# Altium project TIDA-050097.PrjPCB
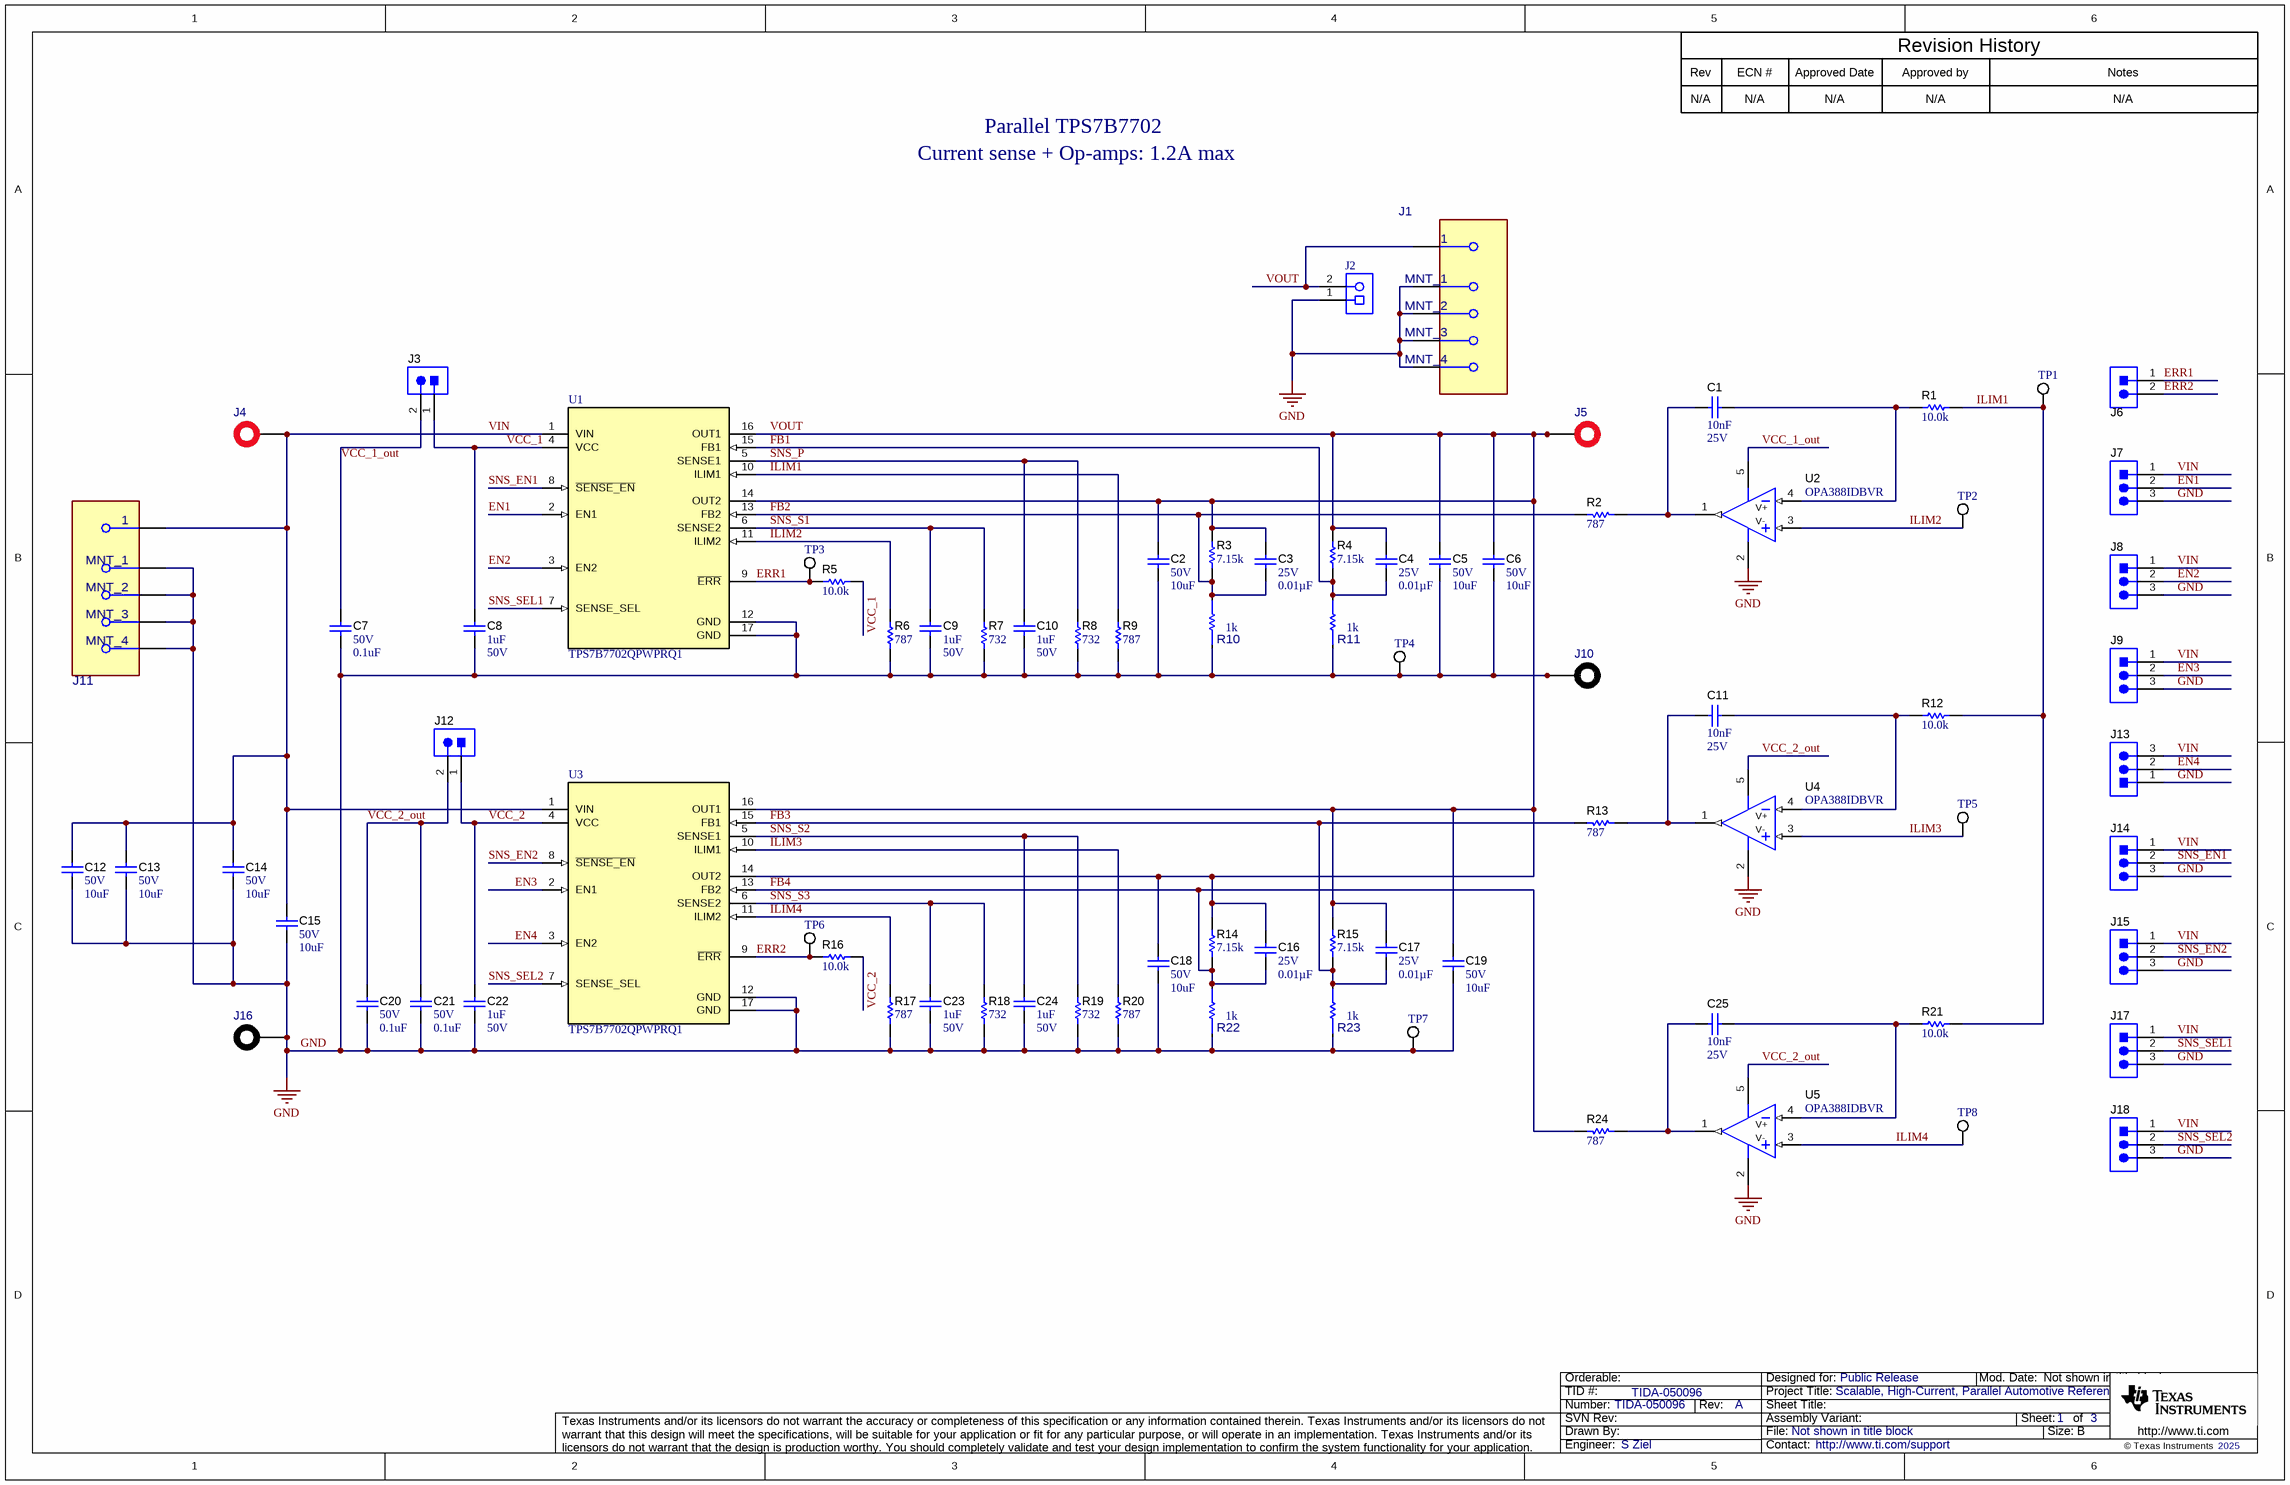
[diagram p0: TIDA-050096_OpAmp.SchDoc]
TID: TIDA-050096; TechSupport: http://www.ti.com/support; SCH_Rev: A; PRJ_Title: Scalable, High-Current, Parallel Automotive Reference Design; PRJ_Number: TIDA-050096; PRJ_Engineer: S Ziel; PRJ_Customer: Public Release; PCB_Rev: A; PCB_Layout: S Ziel; CopyrightYear: 2025
3 sheets, 143 parts. Net scope: global (net labels, ports and power ports of the same name join across sheets).
Board file: TIDA-050096_PCB.PcbDoc
Sheets:
  TIDA-050096_OpAmp.SchDoc
  TIDA-050096_Hardware.SchDoc
  TIDA-050096_Ballast.SchDoc

## Sheet TIDA-050096_OpAmp.SchDoc
size 431 x 279 mm; Date: Not shown in title block; ApprovedBy: Not shown in title block; CheckedBy: Not shown in title block; Author: Not shown in title block; CompanyName: Not shown in title block; Engineer: Not shown in title block; Organization: Not shown in title block; Address1: Not shown in title block; Address2: Not shown in title block; Address3: Not shown in title block; Address4: Not shown in title block; DocumentNumber: 1; Revision: Use project parameter SCH_Rev; SheetNumber: 1; SheetTotal: 3; PageSetup: Record=PageOptions¦CenterHorizontal=True¦CenterVertical=True¦PrintScale=1.00¦XCorrection=1.00¦YCorrection=1.00¦PrintKind=0¦BorderSize=5000000¦LeftOffset=0¦BottomOffset=0¦Orientation=2¦PaperLength=1000¦PaperWidth=1000¦Scale=100¦PaperSource=15¦PrintQuality=600¦MediaType=1¦DitherType=10¦PaperKind=Letter¦PrintScaleMode=1

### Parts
C1  Cap_F: 10nF  VDC_V: 25V  [0402]  (hidden comment: 04023C103JAT2A)
C2  VDC_V: 50V  ValueDisplayed: 10uF  [1210_270]  (hidden comment: GRM32ER71H106KA12L)
C3  VDC_V: 25V  ValueDisplayed: 0.01µF  [0402]  (hidden comment: 04023C103JAT2A)
C4  VDC_V: 25V  ValueDisplayed: 0.01µF  [0402]  (hidden comment: 04023C103JAT2A)
C5  VDC_V: 50V  ValueDisplayed: 10uF  [1210_270]  (hidden comment: GRM32ER71H106KA12L)
C6  VDC_V: 50V  ValueDisplayed: 10uF  [1210_270]  (hidden comment: GRM32ER71H106KA12L)
C7  VDC_V: 50V  ValueDisplayed: 0.1uF  [0402]  (hidden comment: C1005X7R1H104K050BE)
C8  ValueDisplayed: 1uF  VDC_V: 50V  [0603]  (hidden comment: GRM188R61H105KAALD)
C9  ValueDisplayed: 1uF  VDC_V: 50V  [0603]  (hidden comment: GRM188R61H105KAALD)
C10  ValueDisplayed: 1uF  VDC_V: 50V  [0603]  (hidden comment: GRM188R61H105KAALD)
C11  Cap_F: 10nF  VDC_V: 25V  [0402]  (hidden comment: 04023C103JAT2A)
C12  VDC_V: 50V  ValueDisplayed: 10uF  [1210_270]  (hidden comment: GRM32ER71H106KA12L)
C13  VDC_V: 50V  ValueDisplayed: 10uF  [1210_270]  (hidden comment: GRM32ER71H106KA12L)
C14  VDC_V: 50V  ValueDisplayed: 10uF  [1210_270]  (hidden comment: GRM32ER71H106KA12L)
C15  VDC_V: 50V  ValueDisplayed: 10uF  [1210_270]  (hidden comment: GRM32ER71H106KA12L)
C16  VDC_V: 25V  ValueDisplayed: 0.01µF  [0402]  (hidden comment: 04023C103JAT2A)
C17  VDC_V: 25V  ValueDisplayed: 0.01µF  [0402]  (hidden comment: 04023C103JAT2A)
C18  VDC_V: 50V  ValueDisplayed: 10uF  [1210_270]  (hidden comment: GRM32ER71H106KA12L)
C19  VDC_V: 50V  ValueDisplayed: 10uF  [1210_270]  (hidden comment: GRM32ER71H106KA12L)
C20  VDC_V: 50V  ValueDisplayed: 0.1uF  [0402]  (hidden comment: C1005X7R1H104K050BE)
C21  VDC_V: 50V  ValueDisplayed: 0.1uF  [0402]  (hidden comment: C1005X7R1H104K050BE)
C22  ValueDisplayed: 1uF  VDC_V: 50V  [0603]  (hidden comment: GRM188R61H105KAALD)
C23  ValueDisplayed: 1uF  VDC_V: 50V  [0603]  (hidden comment: GRM188R61H105KAALD)
C24  ValueDisplayed: 1uF  VDC_V: 50V  [0603]  (hidden comment: GRM188R61H105KAALD)
C25  Cap_F: 10nF  VDC_V: 25V  [0402]  (hidden comment: 04023C103JAT2A)
J1  RF12-07H-T-00-50-G  [FP-RF12-07H-T-00-50-G_CONN_MMCX-MFG]  (value not drawn)
J2  691 101 710 002  [Wurth_691101710002]  (value not drawn)
J3  PBC02SAAN  [Sullins_PBC02SAAN]  (value not drawn)
J4  571-0500  [571-0500]  (value not drawn)
J5  571-0500  [571-0500]  (value not drawn)
J6  PBC02SAAN  [Sullins_PBC02SAAN]  (value not drawn)
J7  61300311121  [WURTH_61300311121]  (value not drawn)
J8  61300311121  [WURTH_61300311121]  (value not drawn)
J9  61300311121  [WURTH_61300311121]  (value not drawn)
J10  571-0100  [571-0100]  (value not drawn)
J11  RF12-07H-T-00-50-G  [FP-RF12-07H-T-00-50-G_CONN_MMCX-MFG]  (value not drawn)
J12  PBC02SAAN  [Sullins_PBC02SAAN]  (value not drawn)
J13  61300311121  [WURTH_61300311121]  (value not drawn)
J14  61300311121  [WURTH_61300311121]  (value not drawn)
J15  61300311121  [WURTH_61300311121]  (value not drawn)
J16  571-0100  [571-0100]  (value not drawn)
J17  61300311121  [WURTH_61300311121]  (value not drawn)
J18  61300311121  [WURTH_61300311121]  (value not drawn)
R1  ValueDisplayed: 10.0k  [0603]  (hidden comment: RC0603FR-0710KL)
R2  ValueDisplayed: 787  [0603]  (hidden comment: RC0603FR-07787RL)
R3  ValueDisplayed: 7.15k  [0402]  (hidden comment: CRCW04027K15FKED)
R4  ValueDisplayed: 7.15k  [0402]  (hidden comment: CRCW04027K15FKED)
R5  ValueDisplayed: 10.0k  [0603]  (hidden comment: RC0603FR-0710KL)
R6  ValueDisplayed: 787  [0603]  (hidden comment: RC0603FR-07787RL)
R7  ValueDisplayed: 732  [0402]  (hidden comment: CRCW0402732RFKED)
R8  ValueDisplayed: 732  [0402]  (hidden comment: CRCW0402732RFKED)
R9  ValueDisplayed: 787  [0603]  (hidden comment: RC0603FR-07787RL)
R10  value 1k  [FP-RC0402FR-071KL_0402-IPC_A]  (hidden comment: RC0402FR-071KL)
R11  value 1k  [FP-RC0402FR-071KL_0402-IPC_A]  (hidden comment: RC0402FR-071KL)
R12  ValueDisplayed: 10.0k  [0603]  (hidden comment: RC0603FR-0710KL)
R13  ValueDisplayed: 787  [0603]  (hidden comment: RC0603FR-07787RL)
R14  ValueDisplayed: 7.15k  [0402]  (hidden comment: CRCW04027K15FKED)
R15  ValueDisplayed: 7.15k  [0402]  (hidden comment: CRCW04027K15FKED)
R16  ValueDisplayed: 10.0k  [0603]  (hidden comment: RC0603FR-0710KL)
R17  ValueDisplayed: 787  [0603]  (hidden comment: RC0603FR-07787RL)
R18  ValueDisplayed: 732  [0402]  (hidden comment: CRCW0402732RFKED)
R19  ValueDisplayed: 732  [0402]  (hidden comment: CRCW0402732RFKED)
R20  ValueDisplayed: 787  [0603]  (hidden comment: RC0603FR-07787RL)
R21  ValueDisplayed: 10.0k  [0603]  (hidden comment: RC0603FR-0710KL)
R22  value 1k  [FP-RC0402FR-071KL_0402-IPC_A]  (hidden comment: RC0402FR-071KL)
R23  value 1k  [FP-RC0402FR-071KL_0402-IPC_A]  (hidden comment: RC0402FR-071KL)
R24  ValueDisplayed: 787  [0603]  (hidden comment: RC0603FR-07787RL)
TP1  5016  [Testpoint_Keystone_Compact]  (value not drawn)
TP2  5016  [Testpoint_Keystone_Compact]  (value not drawn)
TP3  5016  [Testpoint_Keystone_Compact]  (value not drawn)
TP4  5016  [Testpoint_Keystone_Compact]  (value not drawn)
TP5  5016  [Testpoint_Keystone_Compact]  (value not drawn)
TP6  5016  [Testpoint_Keystone_Compact]  (value not drawn)
TP7  5016  [Testpoint_Keystone_Compact]  (value not drawn)
TP8  5016  [Testpoint_Keystone_Compact]  (value not drawn)
U1  TPS7B7702QPWPRQ1  [PWP0016J_N]
U2  OPA388IDBVR  [DBV0005A_N]
U3  TPS7B7702QPWPRQ1  [PWP0016J_N]
U4  OPA388IDBVR  [DBV0005A_N]
U5  OPA388IDBVR  [DBV0005A_N]

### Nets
GND: C2.2 C5.2 C6.2 C7.2 C8.1 C9.1 C10.1 C12.2 C13.2 C14.2 C15.2 C18.2 C19.2 C20.2 C21.2 C22.2 C23.1 C24.1 J1.2(MNT_1) J1.3(MNT_2) J1.4(MNT_3) J1.5(MNT_4) J2.1 J7.3 J8.3 J9.3 J10.1 J10.2 J11.2(MNT_1) J11.3(MNT_2) J11.4(MNT_3) J11.5(MNT_4) J13.1 J14.3 J15.3 J16.1 J16.2 J17.3 J18.3 R6.1 R7.1 R8.1 R9.1 R10.1 R11.1 R17.1 R18.1 R19.1 R20.1 R22.1 R23.1 TP4.1 TP7.1 U1.12(GND) U1.17(GND) U2.2(V-) U3.12(GND) U3.17(GND) U4.2(V-) U5.2(V-)
EN1: J7.2 U1.2(EN1)
EN2: J8.2 U1.3(EN2)
EN3: J9.2 U3.2(EN1)
EN4: J13.2 U3.3(EN2)
ERR1: J6.1 R5.2 TP3.1 U1.9(~{ERR})
ERR2: J6.2 R16.2 TP6.1 U3.9(~{ERR})
FB1: C4.2 R4.2 R11.2 U1.15(FB1)
FB2: C3.2 R2.2 R3.2 R10.2 U1.13(FB2)
FB3: C17.2 R13.2 R15.2 R23.2 U3.15(FB1)
FB4: C16.2 R14.2 R22.2 R24.2 U3.13(FB2)
ILIM1: R1.1 R9.2 R12.1 R21.1 TP1.1 U1.10(ILIM1)
ILIM2: R6.2 TP2.1 U1.11(ILIM2) U2.3(IN+)
ILIM3: R20.2 TP5.1 U3.10(ILIM1) U4.3(IN+)
ILIM4: R17.2 TP8.1 U3.11(ILIM2) U5.3(IN+)
SNS_EN1: J14.2 U1.8(~{SENSE_EN})
SNS_EN2: J15.2 U3.8(~{SENSE_EN})
SNS_P: C10.2 R8.2 U1.5(SENSE1)
SNS_S1: C9.2 R7.2 U1.6(SENSE2)
SNS_S2: C24.2 R19.2 U3.5(SENSE1)
SNS_S3: C23.2 R18.2 U3.6(SENSE2)
SNS_SEL1: J17.2 U1.7(SENSE_SEL)
SNS_SEL2: J18.2 U3.7(SENSE_SEL)
VCC_1: C8.2 J3.1 R5.1 U1.4(VCC)
VCC_1_out: C7.1 J3.2 U2.5(V+)
VCC_2: C22.1 J12.1 R16.1 U3.4(VCC)
VCC_2_out: C20.1 C21.1 J12.2 U4.5(V+) U5.5(V+)
VIN: C12.1 C13.1 C14.1 C15.1 J4.1 J4.2 J7.1 J8.1 J9.1 J11.1 J13.3 J14.1 J15.1 J17.1 J18.1 U1.1(VIN) U3.1(VIN)
VOUT: C2.1 C3.1 C4.1 C5.1 C6.1 C16.1 C17.1 C18.1 C19.1 J1.1 J2.2 J5.1 J5.2 R3.1 R4.1 R14.1 R15.1 U1.14(OUT2) U1.16(OUT1) U3.14(OUT2) U3.16(OUT1)
NetC1_1: C1.1 R1.2 U2.4(IN-)
NetC1_2: C1.2 R2.1 U2.1(OUT)
NetC11_1: C11.1 R12.2 U4.4(IN-)
NetC11_2: C11.2 R13.1 U4.1(OUT)
NetC25_1: C25.1 R21.2 U5.4(IN-)
NetC25_2: C25.2 R24.1 U5.1(OUT)

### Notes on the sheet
- Rev
- N/A
- ECN #
- Approved Date
- Approved by
- Revision History
- Notes
- Current sense + Op-amps: 1.2A max
- Parallel TPS7B7702

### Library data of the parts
C1 C11 C25 = CMP-0085568-1: CAP, CERM, 0.01 µF, 25 V,+/- 5%, X7R, 0402; Manufacturer: AVX; TaMin_C: -55°C; Polarized: N; SizeAreaWB_mm2: 3; U/M: EA; Value: 0.01uF; TaMax_C: 125°C; SizeZ_mm: 0.6; SizeX_mm: 1; SizeY_mm: 0.5; AEC Category: Q200; ValueDisplayed: 0.01µF
C2 C5 C6 C12-C15 C18 C19 = CMP-0009226-3: CAP, CERM, 10 uF, 50 V, +/- 10%, X7R, 1210; Manufacturer: MuRata; TaMin_C: -55°C; Polarized: N; SizeAreaWB_mm2: 14.7; Value1: Unknown; U/M: EA; Value: 10uF; TaMax_C: 125°C; SizeZ_mm: 2.7; SizeX_mm: 3.2; SizeY_mm: 2.5; Cap_Case: 1210; SizeArea_mm2: 8; Cap_F: 10µF; AEC Category: Q200
C3 C4 C16 C17 = CMP-0085568-1: CAP, CERM, 0.01 µF, 25 V,+/- 5%, X7R, 0402; Manufacturer: AVX; Value: 0.01uF; SizeZ_mm: 0.6; AEC Qualified: N; Cap_F: 10nF; AEC Category: Q200; SizeAreaWB_mm2: 3; SizeArea_mm2: 0.5; TaMin_C: -55°C; U/M: EA; SizeX_mm: 1; TaMax_C: 125°C
C7 C20 C21 = CMP-0064946-2: CAP, CERM, 0.1 uF, 50 V,+/- 10%, X7R, 0402; Manufacturer: TDK; TaMin_C: -55°C; Polarized: N; SizeAreaWB_mm2: 3; Value1: Unknown; U/M: EA; Value: 0.1uF; TaMax_C: 125°C; SizeZ_mm: 0.6; SizeX_mm: 1; SizeY_mm: 0.5; Cap_F: 100nF; AEC Category: Q200
C8-C10 C22-C24 = CMP-0007350-6: CAP, CERM, 1 uF, 50 V, +/- 10%, X5R, 0603; Manufacturer: MuRata; Value1: Unknown; MFG_Status: TI_Obsolete; Polarized: N; Cap_F: 1µF; SizeZ_mm: 1; SizeArea_mm2: 1.28; Value: 1uF; TaMax_C: 85°C; AEC Category: Q200; SizeX_mm: 1.6; SizeY_mm: 0.8; TaMin_C: -55°C; U/M: EA; SizeAreaWB_mm2: 4.68
J1 J11 = CMP-0096285-1: MMCX Connector Jack, Female Socket 50Ohm Through Hole Solder; Manufacturer: Adam Tech; ContactFinish: Gold; Is Female: yes; Dielectric Material: TEFLON; SizeZ_mm: 0.207inch; Impedance: 50Ω; AEC Qualified: No; Conn Orientation: Vertical
J2 = CMP-0054828-1: Terminal Block, 5 mm, 2x1, Tin, TH; Manufacturer: Wurth Elektronik; CNHeader: FALSE; Green_Lifecycle: Active; Green_REACh: Passed; CT: TRUE
J3 J6 J12 = CMP-0054566-1: Header, 100mil, 2x1, Gold, TH; Manufacturer: Sullins Connector Solutions; CNHeader: TRUE; Current_A: 3A; Green_Lifecycle: Active; Shrouded: N; Gender: Male; Green_REACh: Passed; Voltage_V: 1.8kV; Row_Count: 1; Pitch_mm: 2.54; CT: FALSE; Cert_UL: Y
J4 J5 = CMP-0055393-3: Standard Banana Jack, insulated, 10A, red; Manufacturer: DEM Manufacturing; Green_REACh: Incomplete; Green_Lifecycle: Not Set
J7-J9 J13-J15 J17 J18 = CMP-0054796-4: Header, 2.54 mm, 3x1, Gold, TH; Manufacturer: Wurth Elektronik; Green_REACh: Passed; CT: FALSE; CNHeader: TRUE; Green_Lifecycle: Active
J10 J16 = CMP-0055389-3: Standard Banana Jack, insulated, 10A, black; Manufacturer: DEM Manufacturing; Green_REACh: Incomplete; Green_Lifecycle: Not Set
R1 R5 R12 R16 R21 = CMP-0022746-5: RES, 10.0 k, 1%, 0.1 W, 0603; Manufacturer: Yageo; Power_W: 100mW; TempCo: 100 ppm/C; Value_Code: 10k0; Value: 10.0k; EIA_Code: E96; Res_ohm: 10k; SizeX_mm: 1.6; SizeY_mm: 0.8; SizeZ_mm: 1; Value2: 0.1W; SizeArea_mm2: 1.28; AEC Qualified: N; VDC_V: 75V; AEC Category: Q200; SizeAreaWB_mm2: 4.68
R2 R13 R24 = CMP-0023274-5: RES, 787, 1%, 0.1 W, 0603; Manufacturer: Yageo; Power_W: 100mW; Value_Code: 787R; Value: 787; EIA_Code: E96; TempCo: 100 ppm/C; SizeX_mm: 1.6; SizeY_mm: 0.8; SizeZ_mm: 1; Value2: 0.1W; SizeArea_mm2: 1.28; AEC Qualified: N; AEC Category: Q200; VDC_V: 75V; SizeAreaWB_mm2: 4.68
R3 R4 R14 R15 = CMP-0026553-2: RES, 7.15 k, 1%, 0.063 W, AEC-Q200 Grade 0, 0402; Manufacturer: Vishay-Dale; Power_W: 63mW; TempCo: 100 ppm/C; Value_Code: 7k15; Value: 7.15k; EIA_Code: E96; SizeX_mm: 1; SizeY_mm: 0.5; SizeZ_mm: 0.6; Value2: 0.063W; AEC Qualified: Y; VDC_V: 50V; AEC Category: Q200; AEC Grade: 0
R6 R9 R17 R20 = CMP-0023274-5: RES, 787, 1%, 0.1 W, 0603; Manufacturer: Yageo; Power_W: 100mW; TempCo: 100 ppm/C; Value_Code: 787R; Value: 787; EIA_Code: E96; SizeX_mm: 1.6; SizeY_mm: 0.8; SizeZ_mm: 1; Value2: 0.1W; SizeArea_mm2: 1.28; AEC Qualified: N; VDC_V: 75V; AEC Category: Q200; SizeAreaWB_mm2: 4.68
R7 R8 R18 R19 = CMP-0026538-2: RES, 732, 1%, 0.063 W, AEC-Q200 Grade 0, 0402; Manufacturer: Vishay-Dale; Power_W: 63mW; TempCo: 100 ppm/C; Value_Code: 732R; Value: 732; EIA_Code: E96; SizeX_mm: 1; SizeY_mm: 0.5; SizeZ_mm: 0.6; Value2: 0.063W; AEC Qualified: Y; VDC_V: 50V; AEC Category: Q200; AEC Grade: 0
R10 R11 R22 R23 = CMP-0098279-1: RES Thick Film SMD 1kΩ 1% 1/16W 0402 100ppm/°C; Manufacturer: Yageo; Power_W: 63mW; SizeZ_mm: 0.4mm; AEC Qualified: No; VDC_V: 50V; Standoff Height: 0mm
TP1-TP8 = CMP-0055153-1: Test Point, Compact, SMT; Manufacturer: Keystone; CNHeader: FALSE; Green_Lifecycle: Active; Green_REACh: Passed; CT: TRUE
U1 U3 = CMP-0073734-2: Dual-Channel Antenna LDO With Current Sense, PWP0016J (TSSOP-16); Manufacturer: Texas Instruments; SizeX_mm: 6.4; SizeY_mm: 5.0; CompType: IC; SizeZ_mm: 1.2; SizeArea_mm2: 32.0; SizeAreaWB_mm2: 58.8; U/M: EA; Green_Lifecycle: Active; Green_REACh: Passed
U2 U4 U5 = CMP-0860922-1: 10MHz, CMOS, Zero-Drift, Zero-Crossover, True RRIO Precision Operational Amplifier, DBV0005A (SOT-23-5); Manufacturer: Texas Instruments; Alternate PartNumber: OPA388IDBVT; AEC Category: Q200; SizeZ_mm: 1.45; SizeAreaWB_mm2: 14.82; AEC Qualified: N; CompType: IC; Rating: Catalog; SizeArea_mm2: 8.12; SizeX_mm: 2.8; SizeY_mm: 2.9

## Sheet TIDA-050096_Hardware.SchDoc
size 431 x 279 mm; Date: Not shown in title block; ApprovedBy: Not shown in title block; CheckedBy: Not shown in title block; Author: Not shown in title block; CompanyName: Not shown in title block; Engineer: Not shown in title block; Organization: Not shown in title block; Address1: Not shown in title block; Address2: Not shown in title block; Address3: Not shown in title block; Address4: Not shown in title block; DocumentNumber: 3; Revision: Use project parameter SCH_Rev; SheetNumber: 3; SheetTotal: 3; PageSetup: Record=PageOptions¦CenterHorizontal=True¦CenterVertical=True¦PrintScale=1.00¦XCorrection=1.00¦YCorrection=1.00¦PrintKind=0¦BorderSize=5000000¦LeftOffset=0¦BottomOffset=0¦Orientation=2¦PaperLength=1000¦PaperWidth=1000¦Scale=100¦PaperSource=15¦PrintQuality=600¦MediaType=1¦DitherType=10¦PaperKind=Letter¦PrintScaleMode=1
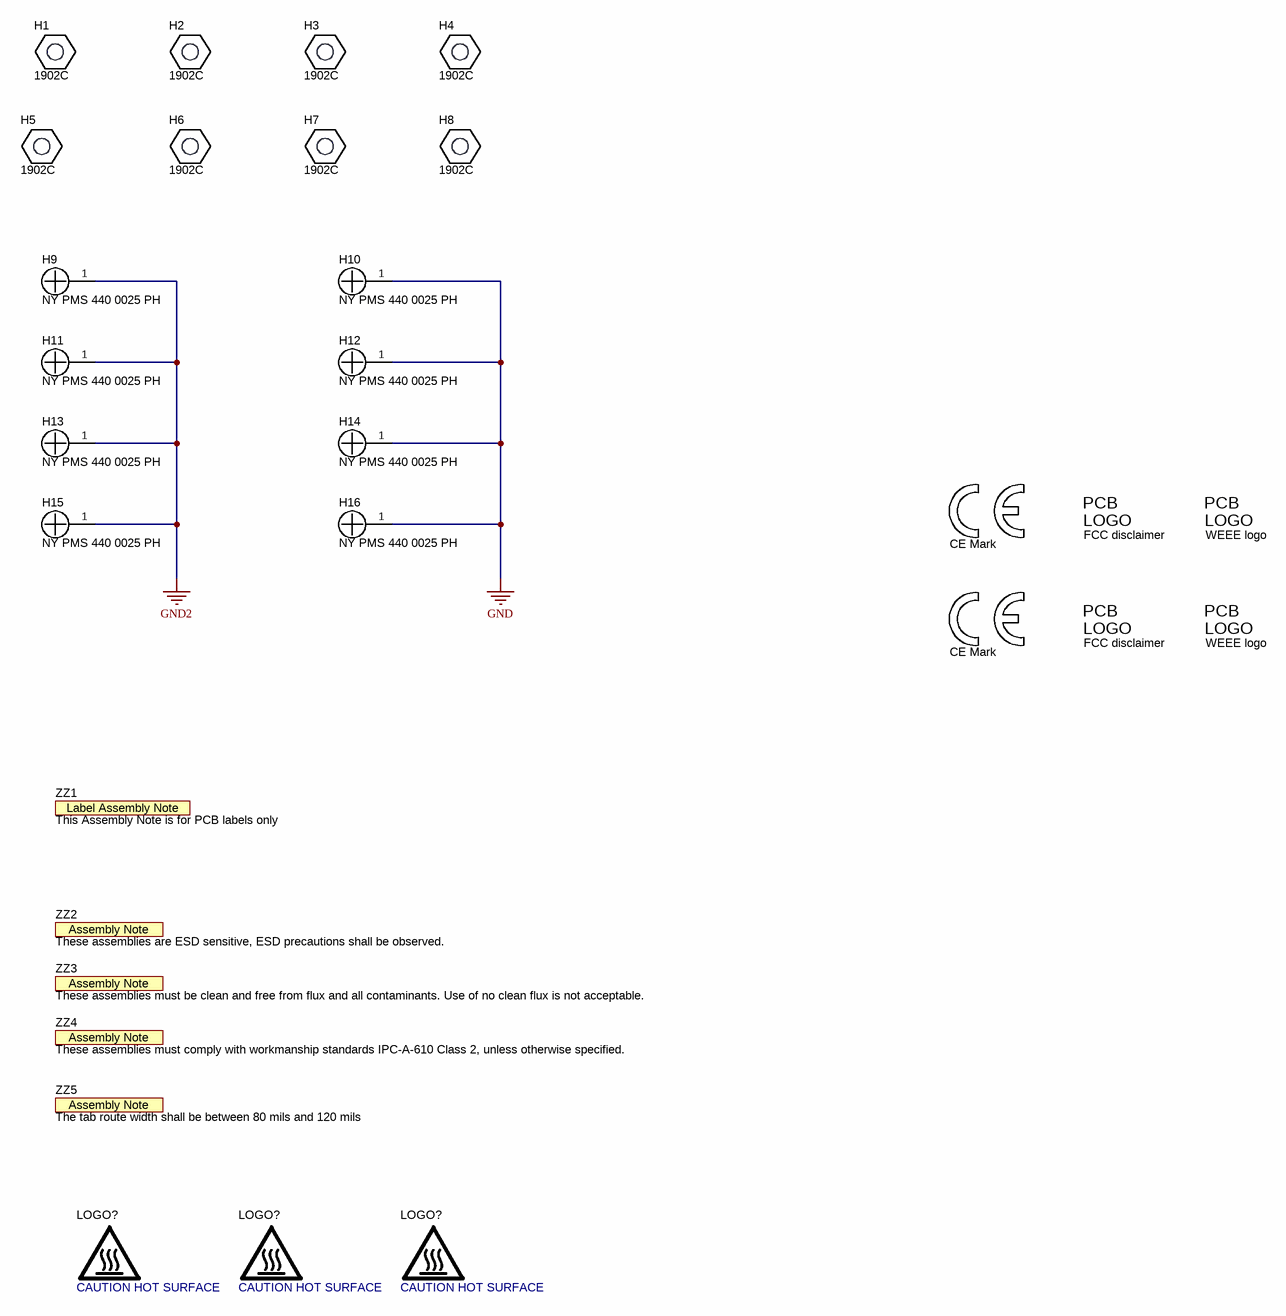
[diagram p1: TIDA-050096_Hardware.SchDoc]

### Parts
(Parts that share a designator on the sheet are numbered #1, #2 ... from top to bottom, then left to right.)
H1  1902C  [Keystone_1902C]
H2  1902C  [Keystone_1902C]
H3  1902C  [Keystone_1902C]
H4  1902C  [Keystone_1902C]
H5  1902C  [Keystone_1902C]
H6  1902C  [Keystone_1902C]
H7  1902C  [Keystone_1902C]
H8  1902C  [Keystone_1902C]
H9  NY PMS 440 0025 PH  [NY PMS 440 0025 PH]
H10  NY PMS 440 0025 PH  [NY PMS 440 0025 PH]
H11  NY PMS 440 0025 PH  [NY PMS 440 0025 PH]
H12  NY PMS 440 0025 PH  [NY PMS 440 0025 PH]
H13  NY PMS 440 0025 PH  [NY PMS 440 0025 PH]
H14  NY PMS 440 0025 PH  [NY PMS 440 0025 PH]
H15  NY PMS 440 0025 PH  [NY PMS 440 0025 PH]
H16  NY PMS 440 0025 PH  [NY PMS 440 0025 PH]
Logo1  CE Mark  [CE_Mark_5mm]  (no BOM)
Logo3  FCC disclaimer  [FCC_disclaimer]  (no BOM)
Logo4  WEEE logo  [WEEE_Minimum]  (no BOM)
Logo5  CE Mark  [CE_Mark_5mm]  (no BOM)
Logo7  FCC disclaimer  [FCC_disclaimer]  (no BOM)
Logo8  WEEE logo  [WEEE_Minimum]  (no BOM)
LOGO?#1  CAUTION HOT SURFACE  [IEC_HotSurface_Small]  (no BOM)
LOGO?#2  CAUTION HOT SURFACE  [IEC_HotSurface_Small]  (no BOM)
LOGO?#3  CAUTION HOT SURFACE  [IEC_HotSurface_Small]  (no BOM)
ZZ1  This Assembly Note is for PCB labels only  [AssemblyNoteLabel]  (no BOM)
ZZ2  These assemblies are ESD sensitive, ESD precautions shall be observed.  [AssemblyNote]  (no BOM)
ZZ3  These assemblies must be clean and free from flux and all contaminants. Use of no clean flux is not acceptable.  [AssemblyNote]  (no BOM)
ZZ4  These assemblies must comply with workmanship standards IPC-A-610 Class 2, unless otherwise specified.  [AssemblyNote]  (no BOM)
ZZ5  The tab route width shall be between 80 mils and 120 mils  [AssemblyNote]  (no BOM)

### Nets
GND: H10.1 H12.1 H14.1 H16.1
GND2: H9.1 H11.1 H13.1 H15.1

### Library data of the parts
H1-H8 = CMP-0003610-1: Standoff, Hex, 0.5"L #4-40 Nylon; Manufacturer: Keystone; CompType: Hardware
H9-H16 = CMP-0003617-1: Machine Screw, Round, #4-40 x 1/4, Nylon, Philips panhead; Manufacturer: B&F Fastener Supply; CompType: Hardware
Logo1 Logo5 = CMP-0074844-1: SymbolCreator: a0412235
Logo3 Logo7 = CMP-0074847-1: FCC_disclaimer; Library Reference: Logo
Logo4 Logo8 = CMP-0074769-1
LOGO?#1-LOGO?#3 = CMP-0074837-1: IEC 61010-1 Hot Surface Warning; SymbolCreator: a0412235
ZZ1 = CMP-0003616-3
ZZ2 = CMP-0077236-1
ZZ3 = CMP-0077237-1
ZZ4 = CMP-0077238-1
ZZ5 = CMP-0077238-1: These assemblies must comply with workmanship standards IPC-A-610 Class 2, unless otherwise specified.

## Sheet TIDA-050096_Ballast.SchDoc
size 431 x 279 mm; Date: Not shown in title block; ApprovedBy: Not shown in title block; CheckedBy: Not shown in title block; Author: Not shown in title block; CompanyName: Not shown in title block; Engineer: Not shown in title block; Organization: Not shown in title block; Address1: Not shown in title block; Address2: Not shown in title block; Address3: Not shown in title block; Address4: Not shown in title block; DocumentNumber: 2; Revision: Use project parameter SCH_Rev; SheetNumber: 2; SheetTotal: 3; PageSetup: Record=PageOptions¦CenterHorizontal=True¦CenterVertical=True¦PrintScale=1.00¦XCorrection=1.00¦YCorrection=1.00¦PrintKind=0¦BorderSize=5000000¦LeftOffset=0¦BottomOffset=0¦Orientation=2¦PaperLength=1000¦PaperWidth=1000¦Scale=100¦PaperSource=15¦PrintQuality=600¦MediaType=1¦DitherType=10¦PaperKind=Letter¦PrintScaleMode=1
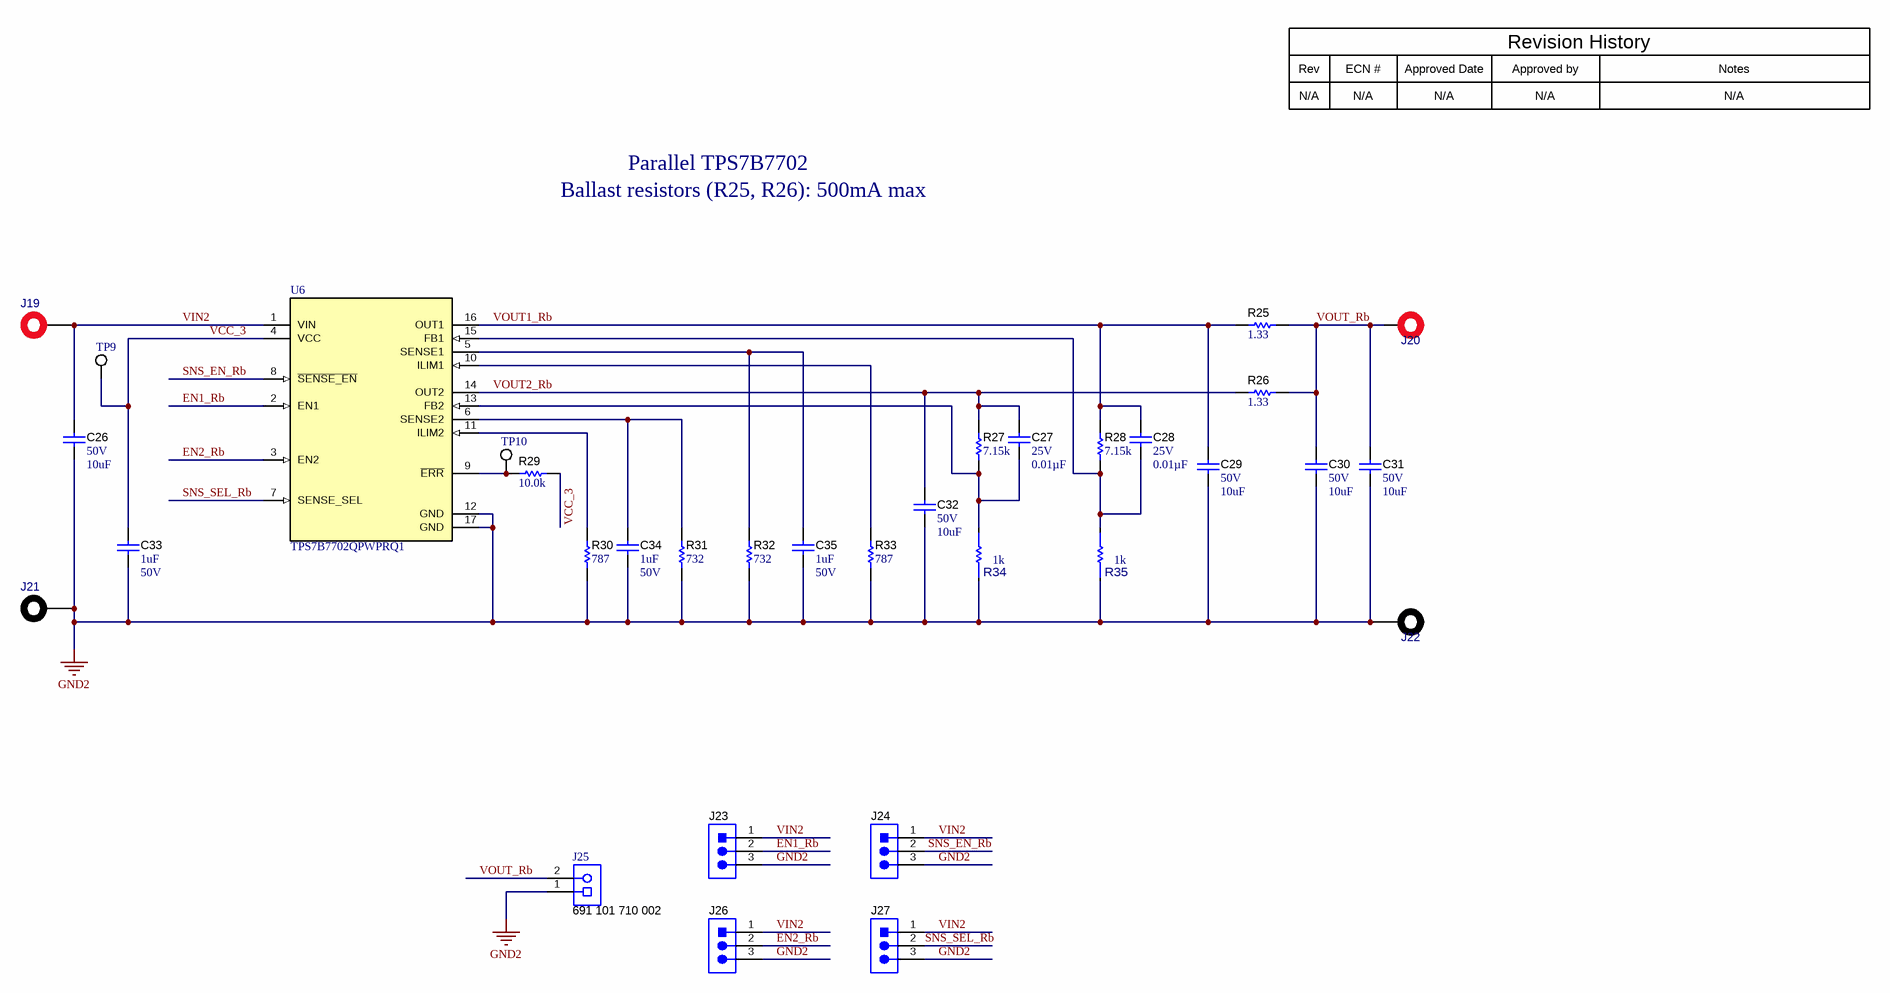
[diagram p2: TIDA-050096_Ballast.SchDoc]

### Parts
C26  VDC_V: 50V  ValueDisplayed: 10uF  [1210_270]  (hidden comment: GRM32ER71H106KA12L)
C27  VDC_V: 25V  ValueDisplayed: 0.01µF  [0402]  (hidden comment: 04023C103JAT2A)
C28  VDC_V: 25V  ValueDisplayed: 0.01µF  [0402]  (hidden comment: 04023C103JAT2A)
C29  VDC_V: 50V  ValueDisplayed: 10uF  [1210_270]  (hidden comment: GRM32ER71H106KA12L)
C30  VDC_V: 50V  ValueDisplayed: 10uF  [1210_270]  (hidden comment: GRM32ER71H106KA12L)
C31  VDC_V: 50V  ValueDisplayed: 10uF  [1210_270]  (hidden comment: GRM32ER71H106KA12L)
C32  VDC_V: 50V  ValueDisplayed: 10uF  [1210_270]  (hidden comment: GRM32ER71H106KA12L)
C33  ValueDisplayed: 1uF  VDC_V: 50V  [0603]  (hidden comment: GRM188R61H105KAALD)
C34  ValueDisplayed: 1uF  VDC_V: 50V  [0603]  (hidden comment: GRM188R61H105KAALD)
C35  ValueDisplayed: 1uF  VDC_V: 50V  [0603]  (hidden comment: GRM188R61H105KAALD)
J19  571-0500  [571-0500]  (value not drawn)
J20  571-0500  [571-0500]  (value not drawn)
J21  571-0100  [571-0100]  (value not drawn)
J22  571-0100  [571-0100]  (value not drawn)
J23  61300311121  [WURTH_61300311121]  (value not drawn)
J24  61300311121  [WURTH_61300311121]  (value not drawn)
J25  691 101 710 002  [Wurth_691101710002]
J26  61300311121  [WURTH_61300311121]  (value not drawn)
J27  61300311121  [WURTH_61300311121]  (value not drawn)
R25  ValueDisplayed: 1.33  [0805_HV]  (hidden comment: RC0805FR-071R33L)
R26  ValueDisplayed: 1.33  [0805_HV]  (hidden comment: RC0805FR-071R33L)
R27  ValueDisplayed: 7.15k  [0402]  (hidden comment: CRCW04027K15FKED)
R28  ValueDisplayed: 7.15k  [0402]  (hidden comment: CRCW04027K15FKED)
R29  ValueDisplayed: 10.0k  [0603]  (hidden comment: RC0603FR-0710KL)
R30  ValueDisplayed: 787  [0603]  (hidden comment: RC0603FR-07787RL)
R31  ValueDisplayed: 732  [0402]  (hidden comment: CRCW0402732RFKED)
R32  ValueDisplayed: 732  [0402]  (hidden comment: CRCW0402732RFKED)
R33  ValueDisplayed: 787  [0603]  (hidden comment: RC0603FR-07787RL)
R34  value 1k  [FP-RC0402FR-071KL_0402-IPC_A]  (hidden comment: RC0402FR-071KL)
R35  value 1k  [FP-RC0402FR-071KL_0402-IPC_A]  (hidden comment: RC0402FR-071KL)
TP9  5016  [Testpoint_Keystone_Compact]  (value not drawn)
TP10  5016  [Testpoint_Keystone_Compact]  (value not drawn)
U6  TPS7B7702QPWPRQ1  [PWP0016J_N]

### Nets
GND2: C26.2 C29.2 C30.2 C31.2 C32.2 C33.2 C34.1 C35.1 J21.1 J21.2 J22.1 J22.2 J23.3 J24.3 J25.1 J26.3 J27.3 R30.1 R31.1 R32.1 R33.1 R34.1 R35.1 U6.12(GND) U6.17(GND)
EN1_Rb: J23.2 U6.2(EN1)
EN2_Rb: J26.2 U6.3(EN2)
SNS_EN_Rb: J24.2 U6.8(~{SENSE_EN})
SNS_SEL_Rb: J27.2 U6.7(SENSE_SEL)
VCC_3: C33.1 R29.1 TP9.1 U6.4(VCC)
VIN2: C26.1 J19.1 J19.2 J23.1 J24.1 J26.1 J27.1 U6.1(VIN)
VOUT1_Rb: C28.1 C29.1 R25.1 R28.1 U6.16(OUT1)
VOUT2_Rb: C27.1 C32.1 R26.1 R27.1 U6.14(OUT2)
VOUT_Rb: C30.1 C31.1 J20.1 J20.2 J25.2 R25.2 R26.2
NetC27_2: C27.2 R27.2 R34.2 U6.13(FB2)
NetC28_2: C28.2 R28.2 R35.2 U6.15(FB1)
NetC34_2: C34.2 R31.2 U6.6(SENSE2)
NetC35_2: C35.2 R32.2 U6.5(SENSE1)
NetR29_2: R29.2 TP10.1 U6.9(~{ERR})
NetR30_2: R30.2 U6.11(ILIM2)
NetR33_2: R33.2 U6.10(ILIM1)

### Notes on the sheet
- Rev
- N/A
- ECN #
- Approved Date
- Approved by
- Revision History
- Notes
- Ballast resistors (R25, R26): 500mA max
- Parallel TPS7B7702

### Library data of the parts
C26 C29-C32 = CMP-0009226-3: as C2 on sheet TIDA-050096_OpAmp
C27 C28 = CMP-0085568-1: as C3 on sheet TIDA-050096_OpAmp
C33-C35 = CMP-0007350-6: as C8 on sheet TIDA-050096_OpAmp
J19 J20 = CMP-0055393-3: as J4 on sheet TIDA-050096_OpAmp
J21 J22 = CMP-0055389-3: as J10 on sheet TIDA-050096_OpAmp
J23 J24 J26 J27 = CMP-0054796-4: as J7 on sheet TIDA-050096_OpAmp
J25 = CMP-0054828-1: as J2 on sheet TIDA-050096_OpAmp
R25 R26 = CMP-0021875-2: RES, 1.33, 1%, 0.125 W, 0805; Manufacturer: Yageo America; Power_W: 125mW; TempCo: 200 ppm/C; Value_Code: 1R33; U/M: EA; Value: 1.33; EIA_Code: E96; SizeX_mm: 2; SizeY_mm: 1.25; SizeZ_mm: 1.45; Value2: 0.125W; SizeArea_mm2: 2.5; VDC_V: 150V; AEC Category: Q200
R27 R28 = CMP-0026553-2: as R3 on sheet TIDA-050096_OpAmp
R29 = CMP-0022746-5: as R1 on sheet TIDA-050096_OpAmp
R30 R33 = CMP-0023274-5: as R6 on sheet TIDA-050096_OpAmp
R31 R32 = CMP-0026538-2: as R7 on sheet TIDA-050096_OpAmp
R34 R35 = CMP-0098279-1: as R10 on sheet TIDA-050096_OpAmp
TP9 TP10 = CMP-0055153-1: as TP1 on sheet TIDA-050096_OpAmp
U6 = CMP-0073734-2: as U1 on sheet TIDA-050096_OpAmp

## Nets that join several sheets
GND: TIDA-050096_OpAmp (60 pins), TIDA-050096_Hardware (H10.1 H12.1 H14.1 H16.1)
GND2: TIDA-050096_Hardware (H9.1 H11.1 H13.1 H15.1), TIDA-050096_Ballast (25 pins)

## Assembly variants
001: not fitted C2 C3 C4 C12 C13 C16 C17 C27 C28 C30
